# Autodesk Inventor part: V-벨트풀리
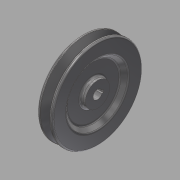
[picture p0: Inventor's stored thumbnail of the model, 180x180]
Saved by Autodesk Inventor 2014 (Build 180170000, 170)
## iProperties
Created: 2015-12
Part Number: V-벨트풀리
Document SubType Name: Modeling
Designer: mdu
Density: 8.08 g/cm^3
Material: 스테인리스강
Appearance: 반광택
Author: mdu
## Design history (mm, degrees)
sketch "스케치1"
  geometry: L1 (-10, 0)-(10, 0); L2 (-10, 0)-(-10, 16); L3 (-10, 16)-(-4, 16); L4 (-4, 16)-(-4, 35); L5 (-4, 35)-(-10, 41); L6 (-10, 41)-(-10, 59.5); L7 (-10, 59.5)-(-6.062, 59.5); L8 (-6.062, 59.5)-(-2.001, 47); L9 (-2.001, 47)-(2.001, 47); L10 (2.001, 47)-(6.062, 59.5); L11 (6.062, 59.5)-(10, 59.5); L12 (10, 59.5)-(10, 41); L13 (10, 41)-(4, 35); L14 (4, 35)-(4, 16); L15 (4, 16)-(10, 16); L16 (10, 16)-(10, 0); L17 (-4.6, 55)-(4.6, 55); 2 further points
  constraints: 34 end point, 7 parallel, 6 equal length, 5 collinear, 3 perpendicular, 2 point on line, 1 coincident, 1 horizontal, 1 midpoint
  dimensions: "d0" = 20 distance of L1.start L1.end; "d1" = 9.2 distance of L17.start L17.end; "d2" = 36 deg angle of L10 L8; "d3" = 4.5 distance between parallel lines of L7 L17; "d4" = 8 distance between parallel lines of L9 L17; "d6" = 110 diameter of L17 L1; "d7" = 32 diameter of L3 L1; "d8" = 82 diameter of L5.end L1; "d9" = 6 distance of L2.end L3.end; "d10" = 135 deg angle of L4 L5
revolve "회전1" sketch "스케치1" stored, may be unused: angle "d11" = 90 deg
fillet "모깎기1" dims "d12" = 2, "d13" = 0.5, "d14" = 1, "d15" = 3
sketch "스케치2"
  geometry: L1 (-2, 5.657)-(-2, 7.8); L2 (-2, 7.8)-(2, 7.8); L3 (2, 7.8)-(2, 5.657); A1 r 6 centre (0, 0) between (-2, 5.657) and (2, 5.657); 1 further point
  constraints: 6 end point, 2 parallel, 2 point on circle, 1 centre point, 1 coincident, 1 perpendicular, 1 vertical
  dimensions: "d16" = 12 diameter of A1; "d17" = 4 distance of L1.end L2.end; "d18" = 13.8 dimension on A1 L2 (computed from d16)
extrude "돌출1" cut sketch "스케치2" stored distance "d19" = 10; taper "d20" = 0 deg
node "솔리드1"
